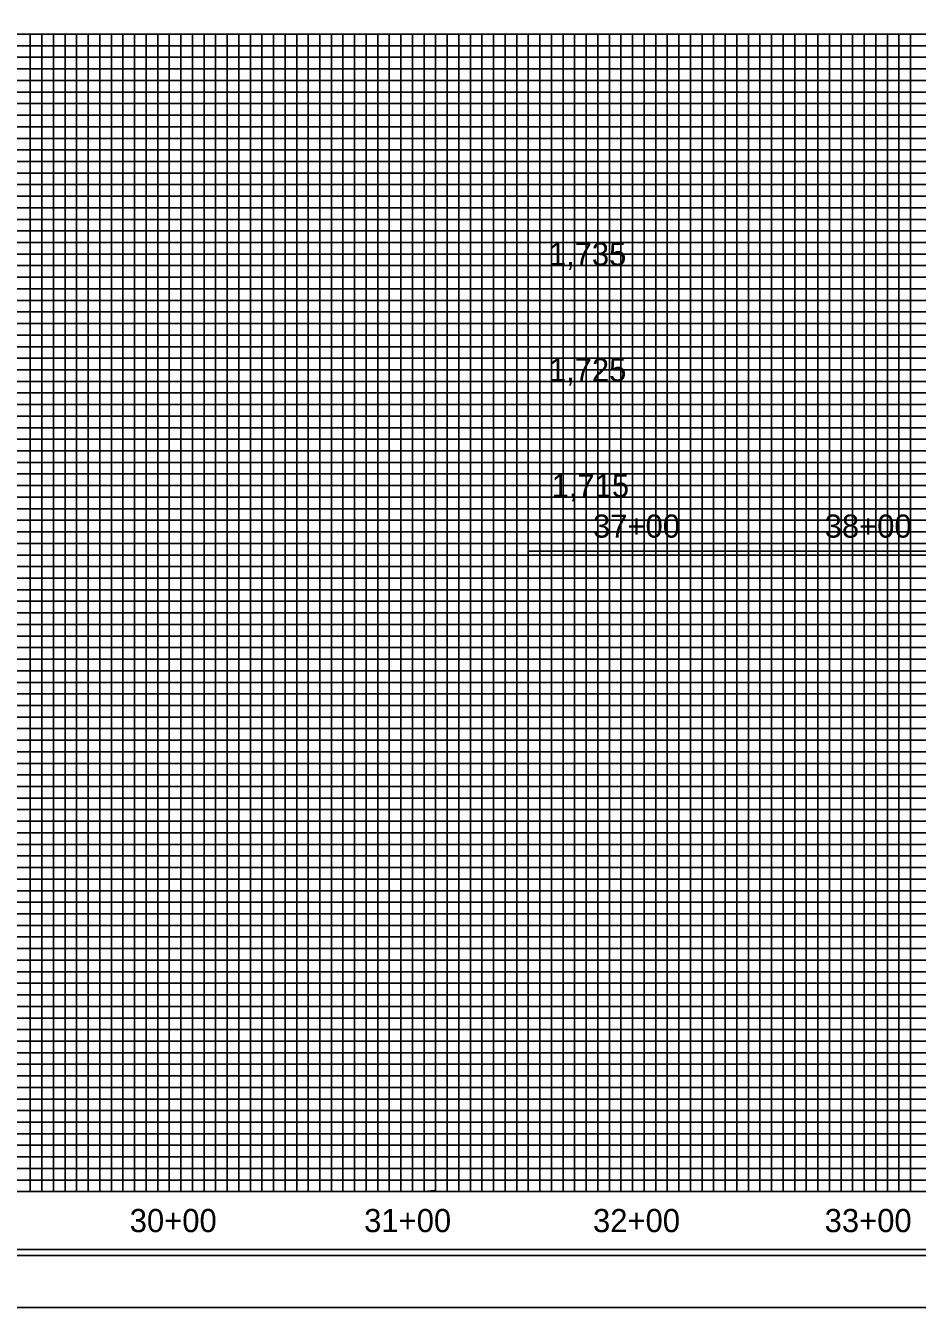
# Model space of a CAD drawing. Extents: x 505692 to 507376, y 438761 to 439861.
# Drawn here: x 506542 to 506927, y 438761 to 439315 of the extents above; entities that cross this region are included whole.
import ezdxf

# ---------------------------------------------------------------- set-up
doc = ezdxf.new("R2010")
doc.units = 0
for name, color, linetype in [('Exist Vertical Profile Vertical Axis Label', 7, 'Continuous'), ('Prop Grid Mask', 7, 'Continuous'), ('Sheet DOT Grid CELL', 7, 'Continuous'), ('Sheet Layout Profile Border Port 2', 7, 'Continuous'), ('Sheet Plot Border Inside CELL', 7, 'Continuous'), ('Sheet Plot Border Outside CELL', 7, 'Continuous'), ('Sheet Profile CELL', 7, 'Continuous'), ('Sheet Profile Grid Major CELL', 7, 'Continuous'), ('Sheet Profile Grid Middle CELL', 7, 'Continuous'), ('Sheet Profile Grid Minor CELL', 7, 'Continuous')]:
    doc.layers.add(name, color=color, linetype=linetype)

msp = doc.modelspace()

# ---------------------------------------------------------------- linework, layer by layer
at = {"layer": 'Prop Grid Mask'}
msp.add_lwpolyline([(506758.68, 439111.14), (507258.68, 439111.14), (507258.68, 439087.84), (506758.68, 439087.84)], close=True, dxfattribs=at)
at = {"layer": 'Sheet DOT Grid CELL'}
for p, q in [((505858.68, 439311.14), (507358.56, 439311.14)), ((506558.68, 439311.14), (506558.68, 438811.14)), ((506608.68, 439311.14), (506608.68, 438811.14)), ((506658.68, 439311.14), (506658.68, 438811.14)), ((506708.68, 439311.14), (506708.68, 438811.14)), ((506758.68, 439311.14), (506758.68, 438811.14)), ((506808.68, 439311.14), (506808.68, 438811.14)), ((506858.68, 439311.14), (506858.68, 438811.14)), ((506908.68, 439311.14), (506908.68, 438811.14)), ((505858.68, 439261.14), (507358.56, 439261.14)), ((505858.68, 439211.14), (507358.56, 439211.14)), ((505858.68, 439161.14), (507358.56, 439161.14)), ((505858.68, 439111.14), (507358.56, 439111.14)), ((505858.68, 439061.14), (507358.56, 439061.14)), ((505858.68, 439011.14), (507358.56, 439011.14)), ((505858.68, 438961.14), (507358.56, 438961.14)), ((505858.68, 438911.14), (507358.56, 438911.14)), ((505858.68, 438861.14), (507358.56, 438861.14))]:
    msp.add_line(p, q, dxfattribs=at)
at = {"layer": 'Sheet Layout Profile Border Port 2'}
for points in [[(505908.72, 439311.14), (507308.72, 439311.14), (507308.72, 438811.14), (505908.72, 438811.14)], [(506808.68, 439261.14), (507208.68, 439261.14), (507208.68, 439111.14), (506808.68, 439111.14)]]:
    msp.add_lwpolyline(points, close=True, dxfattribs=at)
at = {"layer": 'Sheet Plot Border Inside CELL'}
msp.add_lwpolyline([(505704.68, 438783.59), (507371.18, 438783.59), (507371.18, 439838.69), (505704.68, 439838.69)], close=True, dxfattribs=at)
at = {"layer": 'Sheet Plot Border Outside CELL'}
msp.add_lwpolyline([(505691.68, 438761.14), (507375.68, 438761.14), (507375.68, 439861.14), (505691.68, 439861.14)], close=True, dxfattribs=at)
at = {"layer": 'Sheet Profile CELL'}
for p, q in [((505858.68, 439311.14), (507358.68, 439311.14)), ((506758.68, 439087.84), (506758.68, 439261.14)), ((506758.68, 439261.14), (507258.68, 439261.14)), ((506808.68, 439111.14), (506808.68, 439261.14)), ((506758.68, 439111.14), (507258.68, 439111.14)), ((506758.68, 439087.84), (507258.68, 439087.84)), ((507358.68, 438811.14), (505858.68, 438811.14)), ((505858.68, 438786.14), (507358.68, 438786.14))]:
    msp.add_line(p, q, dxfattribs=at)
msp.add_lwpolyline([(507358.68, 439836.14), (505858.68, 439836.14), (505858.68, 438786.14), (507358.68, 438786.14)], close=True, dxfattribs=at)
at = {"layer": 'Sheet Profile Grid Major CELL'}
for p, q in [((506558.68, 439311.14), (506608.68, 439311.14)), ((506558.68, 439311.14), (506608.68, 439311.14)), ((506658.68, 439311.14), (506708.68, 439311.14)), ((506658.68, 439311.14), (506708.68, 439311.14)), ((506758.68, 439311.14), (506808.68, 439311.14)), ((506758.68, 439311.14), (506808.68, 439311.14)), ((506858.68, 439311.14), (506908.68, 439311.14)), ((506858.68, 439311.14), (506908.68, 439311.14))]:
    msp.add_line(p, q, dxfattribs=at)
for points in [[(506508.68, 438811.14), (506558.68, 438811.14), (506558.68, 439311.14), (506608.68, 439311.14), (506608.68, 438811.14), (506658.68, 438811.14), (506658.68, 439311.14), (506708.68, 439311.14), (506708.68, 438811.14), (506758.68, 438811.14), (506758.68, 439311.14), (506808.68, 439311.14), (506808.68, 438811.14), (506858.68, 438811.14), (506858.68, 439311.14), (506908.68, 439311.14), (506908.68, 438811.14), (506958.68, 438811.14)], [(507358.68, 439261.14), (505858.68, 439261.14)], [(507358.68, 439211.14), (505858.68, 439211.14), (505858.68, 439161.14), (507358.68, 439161.14)], [(507358.68, 439111.14), (505858.68, 439111.14), (505858.68, 439061.14), (507358.68, 439061.14)], [(507358.68, 439011.14), (505858.68, 439011.14), (505858.68, 438961.14), (507358.68, 438961.14)], [(507358.68, 438911.14), (505858.68, 438911.14), (505858.68, 438911.14), (505858.68, 438861.14), (507358.68, 438861.14)], [(507358.68, 438811.14), (505858.68, 438811.14)]]:
    msp.add_lwpolyline(points, dxfattribs=at)
at = {"layer": 'Sheet Profile Grid Middle CELL'}
for points in [[(506533.68, 438811.14), (506583.68, 438811.14), (506583.68, 439311.14), (506633.68, 439311.14), (506633.68, 438811.14), (506683.68, 438811.14), (506683.68, 439311.14), (506733.68, 439311.14), (506733.68, 438811.14), (506783.68, 438811.14), (506783.68, 439311.14), (506833.68, 439311.14), (506833.68, 438811.14), (506883.68, 438811.14), (506883.68, 439311.14), (506933.68, 439311.14)], [(505858.68, 439286.14), (507358.68, 439286.14)], [(507358.68, 439236.14), (505858.68, 439236.14), (505858.68, 439186.14), (507358.68, 439186.14)], [(507358.68, 439136.14), (505858.68, 439136.14), (505858.68, 439086.14), (507358.68, 439086.14)], [(507358.68, 439036.14), (505858.68, 439036.14), (505858.68, 438986.14), (507358.68, 438986.14)], [(507358.68, 438936.14), (505858.68, 438936.14), (505858.68, 438886.14), (507358.68, 438886.14)], [(507358.68, 438836.14), (505858.68, 438836.14)]]:
    msp.add_lwpolyline(points, dxfattribs=at)
at = {"layer": 'Sheet Profile Grid Minor CELL'}
for p, q in [((505908.68, 439306.14), (507308.68, 439306.14)), ((507308.68, 439301.14), (505908.68, 439301.14)), ((505908.68, 439296.14), (507308.68, 439296.14)), ((507308.68, 439291.14), (505908.68, 439291.14)), ((505908.68, 439281.14), (507308.68, 439281.14)), ((507308.68, 439276.14), (505908.68, 439276.14)), ((505908.68, 439271.14), (507308.68, 439271.14)), ((507308.68, 439266.14), (505908.68, 439266.14)), ((505908.68, 439256.14), (507308.68, 439256.14)), ((507308.68, 439251.14), (505908.68, 439251.14)), ((505908.68, 439246.14), (507308.68, 439246.14)), ((507308.68, 439241.14), (505908.68, 439241.14)), ((505908.68, 439231.14), (507308.68, 439231.14)), ((507308.68, 439226.14), (505908.68, 439226.14)), ((505908.68, 439221.14), (507308.68, 439221.14)), ((507308.68, 439216.14), (505908.68, 439216.14)), ((505908.68, 439206.14), (507308.68, 439206.14)), ((507308.68, 439201.14), (505908.68, 439201.14)), ((505908.68, 439196.14), (507308.68, 439196.14)), ((507308.68, 439191.14), (505908.68, 439191.14)), ((505908.68, 439181.14), (507308.68, 439181.14)), ((507308.68, 439176.14), (505908.68, 439176.14)), ((505908.68, 439171.14), (507308.68, 439171.14)), ((507308.68, 439166.14), (505908.68, 439166.14)), ((505908.68, 439156.14), (507308.68, 439156.14)), ((507308.68, 439151.14), (505908.68, 439151.14)), ((505908.68, 439146.14), (507308.68, 439146.14)), ((507308.68, 439141.14), (505908.68, 439141.14)), ((505908.68, 439131.14), (507308.68, 439131.14)), ((507308.68, 439126.14), (505908.68, 439126.14)), ((505908.68, 439121.14), (507308.68, 439121.14)), ((507308.68, 439116.14), (505908.68, 439116.29)), ((505908.68, 439106.14), (507308.68, 439106.14)), ((507308.68, 439101.14), (505908.68, 439101.14)), ((505908.68, 439096.14), (507308.68, 439096.14)), ((507308.68, 439091.14), (505908.68, 439091.14)), ((505908.68, 439081.14), (507308.68, 439081.14)), ((507308.68, 439076.14), (505908.68, 439076.14)), ((505908.68, 439071.14), (507308.68, 439071.14)), ((507308.68, 439066.14), (505908.68, 439066.14)), ((505908.68, 439056.14), (507308.68, 439056.14)), ((507308.68, 439051.14), (505908.68, 439051.14)), ((505908.68, 439046.14), (507308.68, 439046.14)), ((507308.68, 439041.14), (505908.68, 439041.14)), ((505908.68, 439031.14), (507308.68, 439031.14)), ((507308.68, 439026.14), (505908.68, 439026.14)), ((505908.68, 439021.14), (507308.68, 439021.14)), ((507308.68, 439016.14), (505908.68, 439016.14)), ((505908.68, 439006.14), (507308.68, 439006.14)), ((507308.68, 439001.14), (505908.68, 439001.14)), ((505908.68, 438996.14), (507308.68, 438996.14)), ((507308.68, 438991.14), (505908.68, 438991.14)), ((505908.68, 438981.14), (507308.68, 438981.14)), ((507308.68, 438976.14), (505908.68, 438976.14)), ((505908.68, 438971.14), (507308.68, 438971.14)), ((507308.68, 438966.14), (505908.68, 438966.14)), ((505908.68, 438956.14), (507308.68, 438956.14)), ((507308.68, 438951.14), (505908.68, 438951.14)), ((505908.68, 438946.14), (507308.68, 438946.14)), ((507308.68, 438941.14), (505908.68, 438941.14)), ((505908.68, 438931.14), (507308.68, 438931.14)), ((507308.68, 438926.14), (505908.68, 438926.14)), ((505908.68, 438921.14), (507308.68, 438921.14)), ((507308.68, 438916.14), (505908.68, 438916.14)), ((505908.68, 438906.14), (507308.68, 438906.14)), ((507308.68, 438901.14), (505908.68, 438901.14)), ((505908.68, 438896.14), (507308.68, 438896.14)), ((507308.68, 438891.14), (505908.68, 438891.14)), ((505908.68, 438881.14), (507308.68, 438881.14)), ((507308.68, 438876.14), (505908.68, 438876.14)), ((505908.68, 438871.14), (507308.68, 438871.14)), ((507308.68, 438866.14), (505908.68, 438866.14)), ((505908.68, 438856.14), (507308.68, 438856.14)), ((507308.68, 438851.14), (505908.68, 438851.14)), ((505908.68, 438846.14), (507308.68, 438846.14)), ((507308.68, 438841.14), (505908.68, 438841.14)), ((505908.68, 438831.14), (507308.68, 438831.14)), ((507308.68, 438826.14), (505908.68, 438826.14)), ((505908.68, 438821.14), (507308.68, 438821.14)), ((505908.68, 438816.14), (507308.68, 438816.14))]:
    msp.add_line(p, q, dxfattribs=at)
for points in [[(506538.68, 438811.14), (506543.68, 438811.14), (506543.68, 439311.14), (506548.68, 439311.14), (506548.68, 438811.14), (506553.68, 438811.14), (506553.68, 439311.14), (506563.68, 439311.14), (506563.68, 438811.14), (506563.68, 438811.14), (506568.68, 438811.14), (506568.68, 439311.14), (506573.68, 439311.14), (506573.68, 438811.14), (506578.68, 438811.14), (506578.68, 439311.14), (506588.68, 439311.14), (506588.68, 438811.14), (506593.68, 438811.14), (506593.68, 439311.14), (506598.68, 439311.14), (506598.68, 438811.14), (506603.68, 438811.14), (506603.68, 439311.14), (506613.68, 439311.14), (506613.68, 438811.14), (506618.68, 438811.14), (506618.68, 439311.14), (506623.68, 439311.14), (506623.68, 438811.14), (506628.68, 438811.14), (506628.68, 439311.14), (506638.68, 439311.14), (506638.68, 438811.14), (506643.68, 438811.14), (506643.68, 439311.14), (506648.68, 439311.14), (506648.68, 438811.14), (506653.68, 438811.14), (506653.68, 439311.14), (506663.68, 439311.14), (506663.68, 438811.14), (506668.68, 438811.14), (506668.68, 439311.14), (506673.68, 439311.14), (506673.68, 438811.14), (506678.68, 438811.14), (506678.68, 439311.14), (506688.68, 439311.14), (506688.68, 438811.14), (506693.68, 438811.14), (506693.68, 439311.14), (506698.68, 439311.14), (506698.68, 438811.14), (506703.68, 438811.14), (506703.68, 439311.14), (506713.68, 439311.14), (506713.68, 438811.14), (506718.38, 438811.69), (506718.68, 438811.14), (506718.68, 439311.14), (506723.68, 439311.14), (506723.68, 438811.14), (506728.68, 438811.14), (506728.68, 439311.14), (506738.68, 439311.14), (506738.68, 438811.14), (506743.68, 438811.14)], [(506743.68, 438811.14), (506743.68, 439311.14), (506748.68, 439311.14), (506748.68, 438811.14), (506753.68, 438811.14), (506753.68, 439311.14), (506763.68, 439311.14), (506763.68, 438811.14), (506768.68, 438811.14), (506768.68, 439311.14), (506773.68, 439311.14), (506773.68, 438811.14), (506778.68, 438811.14), (506778.68, 439311.14), (506788.68, 439311.14), (506788.68, 438811.14), (506793.68, 438811.14), (506793.68, 439311.14), (506798.68, 439311.14), (506798.68, 438811.14), (506803.68, 438811.14), (506803.68, 439311.14), (506813.68, 439311.14), (506813.68, 438811.14), (506818.68, 438811.14), (506818.68, 439311.14), (506823.68, 439311.14), (506823.68, 438811.14), (506828.68, 438811.14), (506828.68, 439311.14), (506838.68, 439311.14), (506838.68, 438811.14), (506843.68, 438811.14), (506843.68, 439311.14), (506848.68, 439311.14), (506848.68, 438811.14), (506853.68, 438811.14), (506853.68, 439311.14), (506863.68, 439311.14), (506863.68, 438811.14), (506868.68, 438811.14), (506868.68, 439311.14), (506873.68, 439311.14), (506873.68, 438811.14), (506878.68, 438811.14), (506878.68, 439311.14), (506888.68, 439311.14), (506888.68, 438811.14), (506893.68, 438811.14), (506893.68, 439311.14), (506898.68, 439311.14), (506898.68, 438811.14), (506903.68, 438811.14), (506903.68, 439311.14), (506913.68, 439311.14), (506913.68, 438811.14), (506918.68, 438811.14), (506918.68, 439311.14), (506923.68, 439311.14), (506923.68, 438811.14), (506928.68, 438811.14)]]:
    msp.add_lwpolyline(points, dxfattribs=at)

# ---------------------------------------------------------------- texts
at = {"layer": 'Exist Vertical Profile Vertical Axis Label'}
for s, p in [('1,735', (506767.53, 439211.14)), ('1,725', (506767.53, 439161.14)), ('1,715', (506768.73, 439111.14)), ('37+00', (506786.61, 439093.64)), ('38+00', (506886.61, 439093.64)), ('30+00', (506586.61, 438793.64)), ('31+00', (506687.81, 438793.64)), ('32+00', (506786.61, 438793.64)), ('33+00', (506886.61, 438793.64))]:
    msp.add_text(s, height=10, dxfattribs=at).set_placement(p)

doc.saveas('drawing.dxf')
